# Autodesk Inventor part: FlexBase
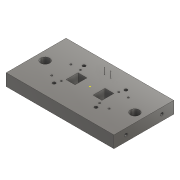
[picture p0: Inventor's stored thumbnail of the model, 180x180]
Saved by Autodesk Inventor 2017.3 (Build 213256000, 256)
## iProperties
Part Number: FlexBase
Material: ステンレス鋼
Document SubType Name: モデリング
Designer: kyushu-hep
Density: 8 g/cm^3
Appearance: 半つや出し
Sheet Metal Rule: Default
Mass: 5352.02 g
Surface Area: 367.335 cm^2
Volume: 277.307 cm^3
Author: kyushu-hep
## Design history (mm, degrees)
sketch "スケッチ1"
  geometry: L1 (-126, 0)-(126, 0) reference; L2 (0, -70)-(0, 70) reference; L3 (90, -50)-(-90, -50); L4 (-90, -50)-(-90, 50); L5 (-90, 50)-(90, 50); L6 (90, 50)-(90, -50); L7 (90, -50)-(-90, 50); L8 (-90, -50)-(90, 50); 1 further point
  constraints: 12 end point, 2 midpoint, 2 parallel, 1 horizontal, 1 perpendicular
  dimensions: "d0" = 180 distance of L4.end L5.end; "d1" = 100 distance of L3.end L4.end
extrude "押し出し1" new body sketch "スケッチ1" distance "d2" = 20; taper "d3" = 0 deg
sketch "スケッチ12"
  geometry: L1 (-90, 50)-(-90, -50) reference; L2 (-90, -50)-(90, -50) reference; C1 r 0.5 at (-5.05, 29.5); C2 r 0.5 at (5.05, 29.5); 1 further point
  constraints: 2 centre point
  dimensions: "d66" = 1 diameter of C1; "d67" = 1 diameter of C2; "d130" = 10.1 distance of C2.centre C1.centre; "d133" = 29.5 vertical distance of point (0, 0) C2.centre; "d134" = 5.05 horizontal distance of C1.centre point (0, 0)
extrude "押し出し9" join sketch "スケッチ12" distance "d72" = 10; taper "d73" = 0 deg
sketch "スケッチ18"
  geometry: L1 (-90, 50)-(-90, -50) reference; L2 (-15, -10)-(-30, -10); L3 (-30, -10)-(-30, 10); L4 (-30, 10)-(-15, 10); L5 (-15, 10)-(-15, -10); L6 (-15, -10)-(-30, 10); L7 (-30, -10)-(-15, 10); L8 (90, -50)-(90, 50) reference; L9 (15, -10)-(30, -10); L10 (30, -10)-(30, 10); L11 (30, 10)-(15, 10); L12 (15, 10)-(15, -10); L13 (15, -10)-(30, 10); L14 (30, -10)-(15, 10); L15 (-90, -50)-(90, -50) reference; 3 further points
  constraints: 24 end point, 4 midpoint, 4 parallel, 2 equal length, 2 horizontal, 2 perpendicular, 1 collinear
  dimensions: "d108" = 15 distance from line of point (0, 0) L5; "d109" = 20 distance of L4.end L2.start; "d135" = 10 distance from line of point (0, 0) L2; "d151" = 15 distance of L2.start L2.end; "d152" = 15 distance from line of L12 point (0, 0)
extrude "押し出し15" cut sketch "スケッチ18" distance "d111" = 30; taper "d112" = 0 deg
sketch "スケッチ22"
  geometry: 1 further point
sketch "スケッチ23"
  geometry: C1 r 7.5 at (-75, 0); C2 r 7.5 at (75, 0); 1 further point
  constraints: 2 centre point
  dimensions: "d181" = 15 diameter of C1; "d184" = 15 diameter of C2; "d200" = 0 vertical distance of point (0, 0) C1.centre; "d201" = 0 vertical distance of C2.centre point (0, 0); "d204" = 75 distance of point (0, 0) C1.centre; "d205" = 75 distance of C2.centre point (0, 0)
sketch "スケッチ24"
  geometry: C1 r 2.5 at (-35, 25); C2 r 2.5 at (35, 25); C3 r 2.5 at (-35, -25); C4 r 2.5 at (35, -25); 2 further points
  constraints: 4 centre point, 1 coincident
  dimensions: "d159" = 5 diameter of C1; "d160" = 25 vertical distance of C1.centre point (0, 0); "d161" = 35 horizontal distance of C1.centre point (0, 0); "d162" = 5 diameter of C2; "d163" = 35 horizontal distance of point (0, 0) C2.centre; "d164" = 25 vertical distance of C2.centre point (0, 0); "d165" = 5 diameter of C3; "d166" = 25 vertical distance of point (0, 0) C3.centre; "d167" = 35 horizontal distance of point (0, 0) C3.centre; "d168" = 5 diameter of C4; "d169" = 25 vertical distance of point (0, 0) C4.centre; "d170" = 35 horizontal distance of point (0, 0) C4.centre
extrude "押し出し19" cut sketch "スケッチ24" distance "d171" = 20; taper "d172" = 0 deg
feature "ねじ4" dims "d173" = 10, "d174" = 0
feature "ねじ5" dims "d175" = 10, "d176" = 0
feature "ねじ6" dims "d177" = 10, "d178" = 0
feature "ねじ7" dims "d179" = 10, "d180" = 0
sketch "スケッチ25"
  geometry: L1 (20, 20)-(-20, 20); L2 (-20, 20)-(-20, -20); L3 (-20, -20)-(20, -20); L4 (20, -20)-(20, 20); L5 (20, 20)-(-20, -20); L6 (-20, 20)-(20, -20); C1 r 1.5 at (-48, -16); C2 r 1.5 at (-48, 16); C3 r 1.5 at (-32, -16); C4 r 1.5 at (-32, 16); C5 r 1.5 at (-16, -16); C6 r 1.5 at (-16, 16); C7 r 1.5 at (0, -16); C8 r 1.5 at (0, 16); C9 r 1.5 at (16, -16); C10 r 1.5 at (16, 16); C11 r 1.5 at (32, -16); C12 r 1.5 at (32, 16); C13 r 1.5 at (48, -16); C14 r 1.5 at (48, 16); 2 further points
  constraints: 14 centre point, 12 end point, 2 horizontal, 2 midpoint, 2 parallel, 1 perpendicular, 1 vertical, 26 other
  dimensions: "d191" = 3 diameter of C1; "d192" = 48 horizontal distance of point (0, 0) C1.centre; "d193" = 16 vertical distance of point (0, 0) C1.centre; "d194" = 40 distance of L3.end L2.end; "d195" = 40 distance of L2.end L1.end; "d196" = 32 distance of C1.centre C2.centre; "d197" = 16 distance of C1.centre C3.centre
extrude "押し出し21" cut sketch "スケッチ25" distance "d198" = 20; taper "d199" = 0 deg
extrude "押し出し22" cut sketch "スケッチ23" distance "d202" = 10; taper "d203" = 0 deg
sketch "スケッチ26"
  geometry: C1 r 2.5 at (-10, 20); C2 r 2.5 at (-10, 80); 1 further point
  constraints: 2 centre point
  dimensions: "d206" = 5 diameter of C1; "d207" = 30 vertical distance of C1.centre point (0, 50); "d208" = 5 diameter of C2; "d209" = 30 vertical distance of C2.centre point (0, 50); "d210" = 10 horizontal distance of C1.centre point (0, 50); "d211" = 10 horizontal distance of C2.centre point (0, 50)
extrude "押し出し23" cut sketch "スケッチ26" distance "d212" = 10; taper "d213" = 0 deg
feature "ねじ8" dims "d214" = 10, "d215" = 0
feature "ねじ9" dims "d216" = 10, "d217" = 0
sketch "スケッチ27"
  geometry: C1 r 2.5 at (10, 80); C2 r 2.5 at (10, 20); 1 further point
  constraints: 2 centre point
  dimensions: "d218" = 5 diameter of C1; "d219" = 5 diameter of C2; "d220" = 30 vertical distance of point (0, 50) C1.centre; "d221" = 30 vertical distance of point (0, 50) C2.centre; "d222" = 10 horizontal distance of point (0, 50) C1.centre; "d223" = 10 horizontal distance of point (0, 50) C2.centre
extrude "押し出し24" cut sketch "スケッチ27" distance "d224" = 10; taper "d225" = 0 deg
feature "ねじ10" dims "d226" = 10, "d227" = 0
feature "ねじ11" dims "d228" = 10, "d229" = 0
node "ソリッド1"
other parameters: "Thickness" = 0.5, "Kファクター" = 4.4, "BendRadius" = 0.5 (= Thickness), "BendReliefWidth" = 0.5 (= Thickness), "BendReliefDepth" = 0.25 (= 0.5 x Thickness), "CornerReliefSize" = 2 (= 4 x Thickness), "SeamGap" = 0.01, "MinimumRemnant" = 1 (= 2 x Thickness), "TransitionRadius" = 0.5 (= BendRadius), "JacobiRadiusSize" = 0.5 (= Thickness), "GapSize" = 0.5 (= Thickness)
